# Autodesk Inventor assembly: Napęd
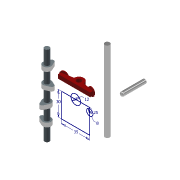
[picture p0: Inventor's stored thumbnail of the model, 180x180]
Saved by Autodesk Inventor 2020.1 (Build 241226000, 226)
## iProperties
Manager: www.cadconsulting.pl
Company: Fabian Stasiak CAD Consulting
Created: 2005-10
Part Number: Napęd
Document SubType Name: Assembly
Designer: F.Stasiak
Author: F.Stasiak
Subject: Zbiór ćwiczeń. Autodesk Inventor 2020. Kurs podstawowy
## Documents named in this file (6)
- C:\2020_Kurs_podstawowy\R6 Zespoły\Wiązania\Napęd\Napęd.iam
- C:\2020_Kurs_podstawowy\R6 Zespoły\Wiązania\Napęd\Szablon.ipt
- C:\2020_Kurs_podstawowy\R6 Zespoły\Wiązania\Napęd\Wałek z krzywkami.ipt
- C:\2020_Kurs_podstawowy\R6 Zespoły\Wiązania\Napęd\Wałek.ipt
- C:\2020_Kurs_podstawowy\R6 Zespoły\Wiązania\Napęd\Popychacz.ipt
- C:\2020_Kurs_podstawowy\R6 Zespoły\Wiązania\Napęd\Trzpień.ipt
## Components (5 placed, 5 different names)
1. Szablon:1
2. Popychacz:1
3. Wałek z krzywkami:1
4. Wałek:1
5. Trzpień:1
